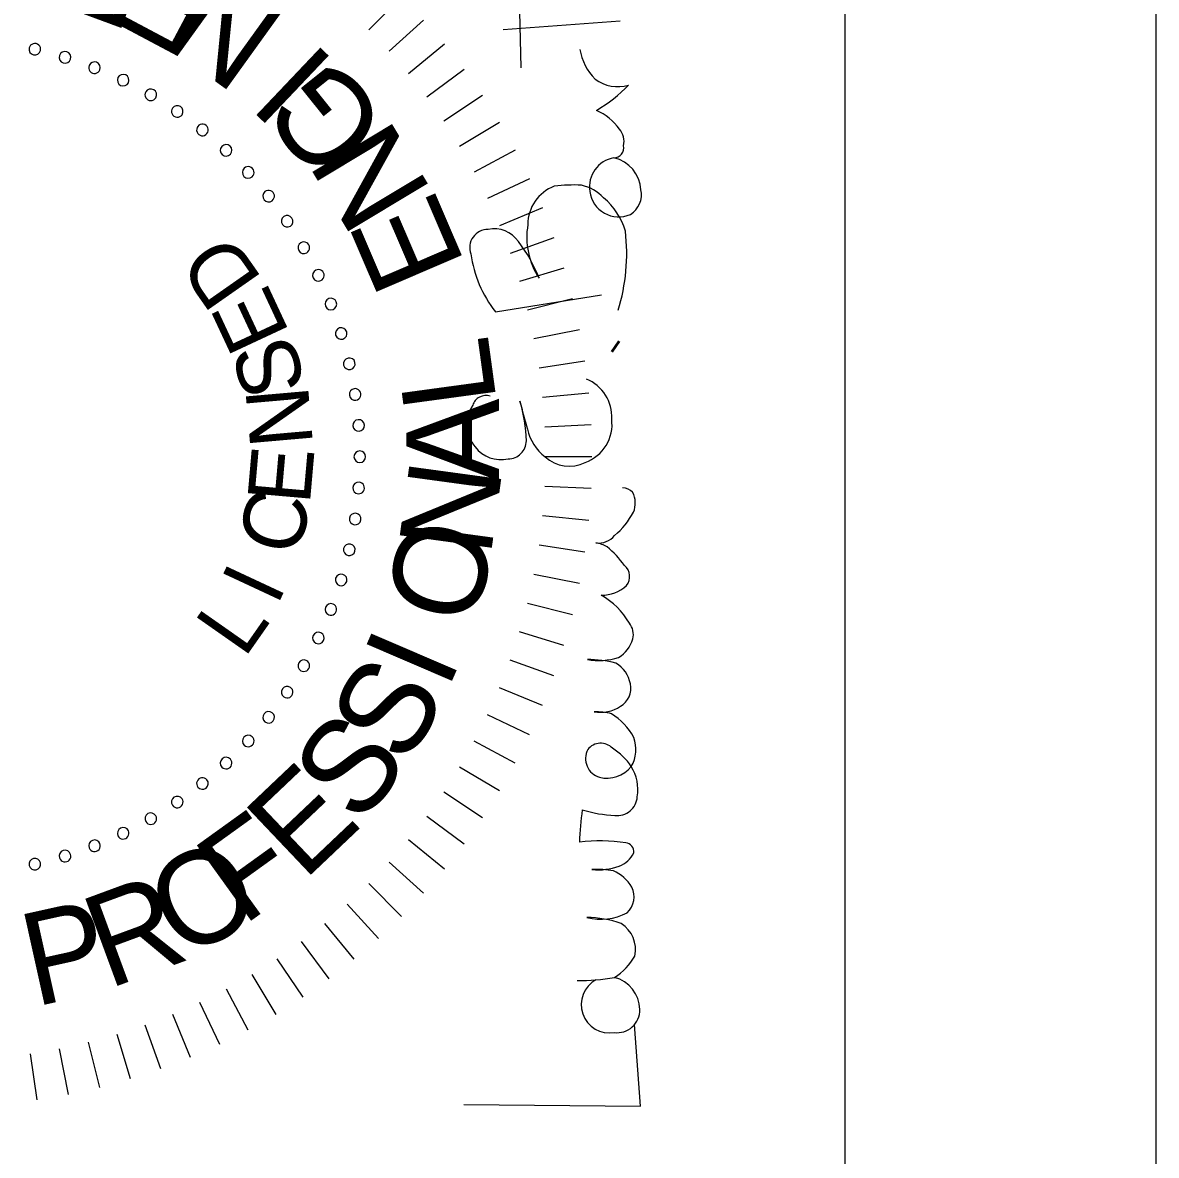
# Model space of a CAD drawing. Extents: x 916887 to 917745, y 329243 to 329793.
# Drawn here: x 917702.44 to 917737.16, y 329615.23 to 329649.92 of the extents above; entities that cross this region are included whole.
import ezdxf

# ---------------------------------------------------------------- set-up
doc = ezdxf.new("R2010")
doc.units = 0
for name, color, linetype in [('Border', 7, 'Continuous'), ('Default', 7, 'Continuous'), ('PLOT BOUNDARY', 7, 'Continuous')]:
    doc.layers.add(name, color=color, linetype=linetype)

# ---------------------------------------------------------------- blocks, each defined once
blk = doc.blocks.new('STAMP')
at = {"layer": 'Default'}
for p, q in [((-0.007878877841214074, 0.0003312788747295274), (-0.0073161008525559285, 0.00041475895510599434)), ((-0.007812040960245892, -5.391156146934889e-05), (-0.007254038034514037, 5.708212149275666e-05)), ((-0.0077263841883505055, -0.0004353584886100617), (-0.0071744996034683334, -0.00029711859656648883)), ((-0.007622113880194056, -0.0008121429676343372), (-0.007077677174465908, -0.0006469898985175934)), ((-0.00749948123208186, -0.0011833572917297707), (-0.0069638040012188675, -0.00099168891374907)), ((-0.007358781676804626, -0.0015481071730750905), (-0.006833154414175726, -0.001330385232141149)), ((-0.007200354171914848, -0.0019055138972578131), (-0.006686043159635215, -0.0016622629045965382)), ((-0.007024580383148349, -0.0022547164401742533), (-0.0065228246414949, -0.001986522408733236)), ((-0.006831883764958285, -0.002594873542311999), (-0.006343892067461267, -0.0023023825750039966)), ((-0.006622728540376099, -0.002925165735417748), (-0.0061496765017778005, -0.0026090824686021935)), ((-0.00639761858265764, -0.0032447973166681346), (-0.005940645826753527, -0.0029058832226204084)), ((-0.006157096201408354, -0.003552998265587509), (-0.005717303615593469, -0.0031920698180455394)), ((-0.005901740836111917, -0.003849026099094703), (-0.005480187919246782, -0.0034669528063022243)), ((-0.0056321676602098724, -0.0041321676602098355), (-0.00522986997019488, -0.003729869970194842)), ((0.00563216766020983, -0.0041321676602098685), (0.0052298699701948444, -0.0037298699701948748)), ((-0.005349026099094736, -0.004401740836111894), (-0.004966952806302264, -0.003980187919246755)), ((0.005349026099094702, -0.004401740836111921), (0.004966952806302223, -0.003980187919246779)), ((-0.0050529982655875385, -0.004657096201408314), (-0.004692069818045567, -0.004217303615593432)), ((0.005052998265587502, -0.004657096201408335), (0.004692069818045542, -0.004217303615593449)), ((-0.004744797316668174, -0.0048976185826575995), (-0.004405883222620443, -0.004440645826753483)), ((0.004744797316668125, -0.0048976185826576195), (0.004405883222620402, -0.0044406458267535)), ((-0.0044251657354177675, -0.005122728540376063), (-0.004109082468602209, -0.004649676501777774)), ((0.004425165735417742, -0.00512272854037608), (0.004109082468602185, -0.004649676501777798)), ((-0.004094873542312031, -0.005331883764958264), (-0.0038023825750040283, -0.004843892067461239)), ((0.0040948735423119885, -0.005331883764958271), (0.003802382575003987, -0.004843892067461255)), ((-0.0037547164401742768, -0.005524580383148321), (-0.0034865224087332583, -0.005022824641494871)), ((0.0037547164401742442, -0.005524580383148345), (0.003486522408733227, -0.005022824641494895)), ((-0.003405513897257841, -0.005700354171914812), (-0.0031622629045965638, -0.0051860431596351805)), ((0.0034055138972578, -0.005700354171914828), (0.003162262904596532, -0.005186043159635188)), ((-0.003048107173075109, -0.005858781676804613), (-0.0028303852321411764, -0.005333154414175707)), ((0.003048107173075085, -0.005858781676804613), (0.002830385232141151, -0.005333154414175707)), ((0.00523613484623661, -0.005376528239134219), (0.005338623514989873, -0.0068089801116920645)), ((-0.0026833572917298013, -0.005999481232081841), (-0.002491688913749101, -0.005463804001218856)), ((0.002683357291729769, -0.005999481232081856), (0.0024916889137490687, -0.005463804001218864)), ((-0.0023121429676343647, -0.006122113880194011), (-0.0021469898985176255, -0.005577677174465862)), ((-0.0019353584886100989, -0.006226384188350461), (-0.0017971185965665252, -0.005674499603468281)), ((0.0019353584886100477, -0.006226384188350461), (0.0017971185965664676, -0.005674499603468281)), ((0.0023121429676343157, -0.006122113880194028), (0.0021469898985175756, -0.005577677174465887)), ((0.004764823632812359, -0.005597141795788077), (0.005863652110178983, -0.005572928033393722)), ((-0.0015539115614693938, -0.006312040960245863), (-0.0014429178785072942, -0.005754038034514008)), ((-0.001168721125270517, -0.006378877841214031), (-0.0010852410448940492, -0.005816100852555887)), ((0.0011687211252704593, -0.006378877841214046), (0.0010852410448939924, -0.005816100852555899)), ((0.0015539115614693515, -0.006312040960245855), (0.0014429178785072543, -0.005754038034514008)), ((-0.0007807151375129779, -0.006426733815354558), (-0.0007249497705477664, -0.0058605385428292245)), ((-0.00039082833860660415, -0.006455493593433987), (-0.00036291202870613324, -0.005887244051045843)), ((-2.0539125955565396e-17, -0.006465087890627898), (-2.0539125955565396e-17, -0.005896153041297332)), ((0.0003908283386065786, -0.0064554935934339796), (0.0003629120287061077, -0.005887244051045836)), ((0.0007807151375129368, -0.006426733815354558), (0.0007249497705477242, -0.005860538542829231)), ((0.001282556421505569, -0.006716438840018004), (0.001411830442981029, -0.006805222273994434)), ((0.0012888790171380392, -0.0067038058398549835), (0.0014181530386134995, -0.006792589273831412))]:
    blk.add_line(p, q, dxfattribs=at)
for points in [[(-0.007938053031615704, -0.004895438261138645), (-0.007956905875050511, -0.007061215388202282), (-0.0069577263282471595, -0.006985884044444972)], [(0.0017747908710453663, -0.005281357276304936), (0.001982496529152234, -0.006583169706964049)]]:
    blk.add_lwpolyline(points, dxfattribs=at)
for centre, radius, start, end in [((-0.0049920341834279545, 0.00036060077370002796), 7.11168561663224e-05, 102.8571428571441, 282.8571428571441), ((-0.0049920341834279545, 0.00036060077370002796), 7.11168561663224e-05, 282.8571428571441, 102.85714285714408), ((0.004992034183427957, 0.00036060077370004), 7.111685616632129e-05, 77.14285714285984, 257.14285714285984), ((0.004992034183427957, 0.00036060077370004), 7.111685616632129e-05, 257.14285714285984, 77.14285714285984), ((-0.004892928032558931, -9.26841668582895e-06), 7.111685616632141e-05, 107.14285714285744, 287.14285714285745), ((-0.004892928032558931, -9.26841668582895e-06), 7.111685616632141e-05, 287.14285714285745, 107.14285714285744), ((0.004892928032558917, -9.268416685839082e-06), 7.111685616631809e-05, 72.85714285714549, 252.8571428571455), ((0.004892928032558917, -9.268416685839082e-06), 7.111685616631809e-05, 252.85714285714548, 72.85714285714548), ((-0.004766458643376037, -0.00037069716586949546), 7.111685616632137e-05, 111.42857142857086, 291.4285714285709), ((-0.004766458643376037, -0.00037069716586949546), 7.111685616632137e-05, 291.4285714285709, 111.42857142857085), ((0.0047664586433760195, -0.00037069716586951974), 7.111685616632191e-05, 68.57142857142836, 248.57142857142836), ((0.0047664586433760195, -0.00037069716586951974), 7.111685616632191e-05, 248.57142857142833, 68.57142857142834), ((-0.0046133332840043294, -0.0007216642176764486), 7.1116856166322e-05, 115.71428571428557, 295.71428571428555), ((-0.0046133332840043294, -0.0007216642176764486), 7.1116856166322e-05, 295.71428571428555, 115.71428571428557), ((0.0046133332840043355, -0.0007216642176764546), 7.111685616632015e-05, 64.28571428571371, 244.2857142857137), ((0.0046133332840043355, -0.0007216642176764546), 7.111685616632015e-05, 244.2857142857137, 64.2857142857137), ((-0.004434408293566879, -0.0010602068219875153), 7.111685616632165e-05, 119.99999999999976, 299.9999999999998), ((-0.004434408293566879, -0.0010602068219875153), 7.111685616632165e-05, 299.9999999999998, 119.99999999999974), ((0.00443440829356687, -0.0010602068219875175), 7.111685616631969e-05, 59.99999999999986, 239.99999999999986), ((0.00443440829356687, -0.0010602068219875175), 7.111685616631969e-05, 239.99999999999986, 59.99999999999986), ((-0.004230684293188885, -0.0013844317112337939), 7.111685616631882e-05, 124.28571428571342, 304.2857142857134), ((-0.004230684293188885, -0.0013844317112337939), 7.111685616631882e-05, 304.2857142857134, 124.28571428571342), ((0.004230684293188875, -0.0013844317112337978), 7.111685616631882e-05, 55.714285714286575, 235.71428571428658), ((0.004230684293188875, -0.0013844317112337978), 7.111685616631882e-05, 235.71428571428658, 55.714285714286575), ((-0.004003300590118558, -0.0016925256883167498), 7.111685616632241e-05, 128.57142857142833, 308.5714285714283), ((-0.004003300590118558, -0.0016925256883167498), 7.111685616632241e-05, 308.5714285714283, 128.57142857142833), ((0.004003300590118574, -0.0016925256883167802), 7.111685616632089e-05, 51.42857142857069, 231.4285714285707), ((0.004003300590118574, -0.0016925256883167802), 7.111685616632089e-05, 231.42857142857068, 51.42857142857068), ((-0.003753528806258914, -0.0019827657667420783), 7.11168561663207e-05, 132.85714285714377, 312.8571428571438), ((-0.003753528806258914, -0.0019827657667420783), 7.11168561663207e-05, 312.85714285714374, 132.85714285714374), ((0.003753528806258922, -0.0019827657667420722), 7.111685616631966e-05, 47.14285714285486, 227.14285714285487), ((0.003753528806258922, -0.0019827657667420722), 7.111685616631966e-05, 227.14285714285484, 47.14285714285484), ((-0.0034827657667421, -0.002253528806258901), 7.111685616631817e-05, 137.14285714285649, 317.1428571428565), ((-0.0034827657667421, -0.002253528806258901), 7.111685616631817e-05, 317.1428571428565, 137.14285714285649), ((0.0034827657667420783, -0.0022535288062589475), 7.111685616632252e-05, 42.857142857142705, 222.85714285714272), ((0.0034827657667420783, -0.0022535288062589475), 7.111685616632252e-05, 222.8571428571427, 42.85714285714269), ((-0.0031925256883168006, -0.0025033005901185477), 7.111685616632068e-05, 141.42857142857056, 321.42857142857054), ((-0.0031925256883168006, -0.0025033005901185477), 7.111685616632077e-05, 321.42857142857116, 141.4285714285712), ((0.0031925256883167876, -0.002503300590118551), 7.111685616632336e-05, 38.57142857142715, 218.57142857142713), ((0.0031925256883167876, -0.002503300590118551), 7.111685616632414e-05, 218.57142857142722, 38.57142857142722), ((-0.0028844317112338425, -0.0027306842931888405), 7.111685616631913e-05, 145.7142857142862, 325.71428571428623), ((-0.0028844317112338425, -0.0027306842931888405), 7.111685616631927e-05, 325.7142857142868, 145.71428571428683), ((0.002884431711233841, -0.0027306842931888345), 7.111685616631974e-05, 34.28571428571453, 214.28571428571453), ((0.002884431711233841, -0.0027306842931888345), 7.111685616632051e-05, 214.28571428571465, 34.28571428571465), ((-0.0025602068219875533, -0.0029344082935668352), 7.111685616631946e-05, 149.99999999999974, 329.9999999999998), ((-0.0025602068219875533, -0.0029344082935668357), 7.111685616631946e-05, 329.9999999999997, 149.99999999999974), ((0.0025602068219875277, -0.0029344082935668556), 7.111685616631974e-05, 30.000000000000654, 210.00000000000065), ((0.0025602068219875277, -0.002934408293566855), 7.111685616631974e-05, 210.00000000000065, 30.000000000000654), ((-0.0022216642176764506, -0.0031133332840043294), 7.111685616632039e-05, 334.2857142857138, 154.2857142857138), ((0.0022216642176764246, -0.0031133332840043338), 7.111685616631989e-05, 25.714285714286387, 205.71428571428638), ((-0.0022216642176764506, -0.0031133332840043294), 7.111685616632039e-05, 154.2857142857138, 334.28571428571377), ((0.0022216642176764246, -0.0031133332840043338), 7.111685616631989e-05, 205.71428571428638, 25.714285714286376), ((-0.0018706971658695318, -0.003266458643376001), 7.111685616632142e-05, 158.57142857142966, 338.5714285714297), ((-0.0018706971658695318, -0.0032664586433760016), 7.111685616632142e-05, 338.57142857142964, 158.57142857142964), ((-0.0015092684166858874, -0.003392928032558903), 7.111685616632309e-05, 342.85714285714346, 162.85714285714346), ((0.0015092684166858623, -0.0033929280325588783), 7.111685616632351e-05, 17.142857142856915, 197.1428571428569), ((0.0018706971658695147, -0.0032664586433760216), 7.111685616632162e-05, 21.428571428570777, 201.42857142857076), ((0.0018706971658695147, -0.0032664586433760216), 7.111685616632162e-05, 201.42857142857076, 21.428571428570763), ((-0.0015092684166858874, -0.003392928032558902), 7.111685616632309e-05, 162.85714285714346, 342.85714285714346), ((-0.0011393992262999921, -0.0034920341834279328), 7.111685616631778e-05, 347.14285714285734, 167.14285714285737), ((0.0011393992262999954, -0.0034920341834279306), 7.111685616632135e-05, 12.857142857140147, 192.85714285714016), ((0.0015092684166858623, -0.0033929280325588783), 7.111685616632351e-05, 197.1428571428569, 17.14285714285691), ((-0.0011393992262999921, -0.0034920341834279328), 7.111685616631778e-05, 167.14285714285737, 347.14285714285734), ((-0.0007631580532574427, -0.003563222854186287), 7.111685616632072e-05, 171.4285714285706, 351.4285714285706), ((-0.0007631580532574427, -0.003563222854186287), 7.111685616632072e-05, 351.4285714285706, 171.4285714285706), ((-0.0003826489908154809, -0.003606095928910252), 7.111685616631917e-05, 175.71428571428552, 355.71428571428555), ((-0.0003826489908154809, -0.003606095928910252), 7.111685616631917e-05, 355.7142857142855, 175.7142857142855), ((-1.2628786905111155e-17, -0.0036204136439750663), 7.111685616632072e-05, 0, 180), ((0.0003826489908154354, -0.0036060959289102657), 7.111685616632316e-05, 4.285714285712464, 184.28571428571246), ((0.0003826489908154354, -0.0036060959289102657), 7.111685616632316e-05, 184.28571428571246, 4.285714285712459), ((0.0007631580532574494, -0.0035632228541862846), 7.111685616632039e-05, 8.571428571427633, 188.57142857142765), ((0.0007631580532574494, -0.0035632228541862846), 7.111685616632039e-05, 188.57142857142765, 8.571428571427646), ((0.0011393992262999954, -0.0034920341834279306), 7.111685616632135e-05, 192.85714285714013, 12.857142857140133), ((-1.2628786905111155e-17, -0.0036204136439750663), 7.111685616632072e-05, 180, 0), ((0.00039604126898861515, -0.005375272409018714), 0.00043958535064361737, 57.64755033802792, 128.97245422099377), ((0.0027009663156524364, -0.006477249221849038), 0.001512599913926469, 98.17812986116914, 127.75649827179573), ((0.0025607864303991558, -0.005191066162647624), 0.0002239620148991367, 359.61429023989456, 109.56218572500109), ((0.00036114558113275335, -0.0053488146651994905), 0.0003972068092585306, 127.45926190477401, 192.9614203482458), ((0.0005805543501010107, -0.005165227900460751), 0.00016909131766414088, 342.3611945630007, 72.54487353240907), ((0.0024288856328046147, -0.00526578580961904), 0.0003633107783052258, 304.8740098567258, 11.625468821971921), ((0.00019608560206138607, -0.005439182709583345), 0.0002220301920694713, 179.67057284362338, 269.694601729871), ((0.0004564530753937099, -0.0062299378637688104), 0.0005678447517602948, 102.0773813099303, 143.39383108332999), ((0.00015503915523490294, -0.003868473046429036), 0.001793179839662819, 271.2738092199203, 287.01217780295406), ((0.002166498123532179, -0.011827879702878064), 0.006419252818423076, 103.3923944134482, 106.55297850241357), ((0.0015502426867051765, -0.00415818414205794), 0.0017765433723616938, 290.99837671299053, 307.69878588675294), ((0.0026896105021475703, -0.006582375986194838), 0.0009159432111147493, 80.29637939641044, 123.29138431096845), ((0.0028457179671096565, -0.006179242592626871), 0.0004997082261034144, 20.58705533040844, 90.19763829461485), ((0.00031613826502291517, -0.006186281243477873), 0.0004319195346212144, 136.9297266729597, 206.7934360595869), ((0.0014539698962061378, -0.006245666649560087), 0.0018752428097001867, 357.2040173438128, 7.418903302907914), ((-0.00671307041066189, -0.006678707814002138), 0.0003465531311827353, 28.430349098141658, 189.68707560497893), ((-0.003955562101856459, -0.006312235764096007), 0.002461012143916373, 179.30402472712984, 190.0665804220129), ((-0.007015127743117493, -0.0065631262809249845), 0.0023079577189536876, 352.1195763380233, 6.249520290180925), ((-0.004786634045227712, -0.009314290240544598), 0.003003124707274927, 81.15725195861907, 88.74550427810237), ((-0.002857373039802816, -0.006810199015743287), 0.001539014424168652, 162.47862001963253, 177.5735090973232), ((-0.0037000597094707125, -0.006623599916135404), 0.00023723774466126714, 61.91684207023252, 163.66717131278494), ((0.0003962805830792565, -0.006217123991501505), 0.0004936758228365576, 199.38474076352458, 277.55079490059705), ((0.0027994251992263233, -0.006216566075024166), 0.0005411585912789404, 313.71200852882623, 347.12598992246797), ((0.005109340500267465, -0.0069995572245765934), 0.000693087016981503, 99.83623703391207, 134.2279465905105), ((-0.007040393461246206, -0.006369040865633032), 0.0013973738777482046, 341.03759348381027, 358.5906169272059), ((-0.004987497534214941, -0.006577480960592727), 0.0006786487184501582, 165.1377733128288, 207.96825790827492), ((-0.006329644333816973, -0.006519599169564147), 0.0012732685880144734, 350.5388137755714, 2.446920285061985), ((-0.004310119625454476, -0.006538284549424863), 0.0007509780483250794, 174.41813129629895, 200.30191948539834), ((-0.0037052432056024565, -0.0065716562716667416), 0.0001960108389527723, 312.7382758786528, 53.40100716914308), ((-0.003974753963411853, -0.006503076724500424), 0.0008496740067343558, 346.26214121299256, 0.7257075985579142), ((-0.002682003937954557, -0.006568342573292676), 0.00044961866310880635, 170.2648919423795, 213.2954708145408), ((-0.00388024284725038, -0.006412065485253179), 0.0013948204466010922, 345.72048696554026, 0.12433676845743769), ((-0.0016914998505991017, -0.006545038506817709), 0.0008054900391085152, 170.27954956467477, 197.78532003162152), ((-0.0013865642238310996, -0.006474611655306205), 0.0003320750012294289, 327.8843366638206, 353.1980671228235), ((-0.0008025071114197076, -0.006544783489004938), 0.0002561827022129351, 173.08541670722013, 230.55848375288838), ((0.0004891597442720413, -0.006207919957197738), 0.0004993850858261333, 266.784921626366, 337.7362429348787), ((0.0032953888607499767, -0.006791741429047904), 0.00035634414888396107, 97.37079091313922, 203.8922211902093), ((0.0033059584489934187, -0.006794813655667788), 0.0003608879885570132, 9.655140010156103, 98.97262191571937), ((0.003588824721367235, -0.00621969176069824), 0.0007209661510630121, 306.1913846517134, 335.23134174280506), ((0.005998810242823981, -0.005456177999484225), 0.0020534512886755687, 211.2594929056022, 225.2513717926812), ((0.004994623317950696, -0.006780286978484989), 0.0004614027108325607, 143.047197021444, 196.91634387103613), ((-0.0035430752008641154, -0.006644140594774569), 0.0003944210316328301, 167.2189950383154, 230.16055614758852), ((-0.002536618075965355, -0.006083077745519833), 0.0009765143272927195, 300.6803608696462, 329.51258202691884), ((-0.0012666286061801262, -0.006594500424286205), 0.00042878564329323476, 177.86300386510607, 223.17874837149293), ((-0.0020051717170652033, -0.0059200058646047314), 0.0011594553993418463, 305.5205731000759, 320.90595982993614), ((0.002532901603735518, -0.0060711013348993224), 0.0008355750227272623, 286.05704557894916, 320.0421489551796), ((-0.006777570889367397, -0.006772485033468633), 0.00027937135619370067, 172.70712454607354, 271.16395527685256), ((-0.006783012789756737, -0.006633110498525), 0.0004188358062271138, 271.5209447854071, 344.87406906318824), ((-0.005754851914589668, -0.006345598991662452), 0.0007393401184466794, 212.4592088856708, 240.63114206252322), ((-0.0055308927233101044, -0.006522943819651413), 0.0005014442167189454, 301.1133493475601, 335.74975916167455), ((-0.004715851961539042, -0.006689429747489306), 0.00031800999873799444, 200.1253724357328, 244.48124886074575), ((-0.004152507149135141, -0.006775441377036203), 0.00024439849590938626, 172.85451562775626, 266.8151593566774), ((-0.00421927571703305, -0.006314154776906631), 0.0007614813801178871, 303.79189499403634, 328.18256979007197), ((-0.0038004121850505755, -0.006299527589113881), 0.000766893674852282, 298.0105046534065, 328.09350966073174), ((-0.00285343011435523, -0.006566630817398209), 0.0003761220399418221, 280.5798823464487, 329.7517392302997), ((-0.0021179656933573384, -0.00658432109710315), 0.00039838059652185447, 211.26450698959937, 253.32703764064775), ((-0.0001785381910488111, -0.0060637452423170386), 0.0010391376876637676, 220.79179678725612, 241.16030041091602), ((0.0024869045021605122, -0.0045618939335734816), 0.0023287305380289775, 252.701645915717, 276.8342307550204), ((0.0032445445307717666, -0.006637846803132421), 0.00042819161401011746, 273.5716384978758, 346.98387133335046), ((0.0037841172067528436, -0.006733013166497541), 0.00012238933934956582, 180.59606692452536, 282.14231124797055), ((0.0038601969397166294, -0.006618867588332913), 0.000239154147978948, 257.8497316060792, 310.1947013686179), ((-0.006036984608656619, -0.006622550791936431), 0.0003760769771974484, 257.6460165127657, 327.7710077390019), ((-0.005391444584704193, -0.006712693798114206), 0.0002677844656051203, 223.12676578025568, 296.5429712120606), ((-0.004842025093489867, -0.006862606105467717), 0.00011432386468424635, 264.56536252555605, 351.47104640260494), ((-0.0028340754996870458, -0.006679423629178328), 0.00026169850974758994, 211.24435430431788, 280.94854976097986), ((-0.0021804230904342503, -0.006741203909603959), 0.00023065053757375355, 257.01114107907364, 308.02112433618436), ((-0.0014677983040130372, -0.006749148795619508), 0.0001780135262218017, 231.21384232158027, 319.94914487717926), ((-0.0005623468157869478, -0.006834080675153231), 0.00018159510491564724, 314.66347430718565, 358.2957841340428), ((0.003211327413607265, -0.006788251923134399), 0.0002833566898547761, 211.44349084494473, 282.2024112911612), ((-0.00407546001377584, -0.006500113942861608), 0.0005271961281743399, 260.1016649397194, 302.042575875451), ((-0.0035868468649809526, -0.00658750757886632), 0.00041578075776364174, 239.8376850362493, 290.64484911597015), ((-0.0005688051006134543, -0.006705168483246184), 0.00029083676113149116, 247.5695171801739, 297.4590386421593)]:
    blk.add_arc(centre, radius, start, end, dxfattribs=at)
for s, height, rotation, p in [('P', 0.0011378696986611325, 282.5, (-0.006741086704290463, 0.00036378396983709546)), ('E', 0.0011378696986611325, 69.75, (0.006276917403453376, -0.001210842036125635)), ('R', 0.0011378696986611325, 290.25, (-0.00652629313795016, -0.0005348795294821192)), ('E', 0.0011378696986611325, 62, (0.005854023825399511, -0.002032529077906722)), ('O', 0.0011378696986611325, 298, (-0.006169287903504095, -0.0014396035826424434)), ('N', 0.001137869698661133, 54.25000000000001, (0.005352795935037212, -0.0027499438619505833)), ('D', 0.0007680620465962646, 34.99999999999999, (0.002169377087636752, -0.0024365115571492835)), ('F', 0.001137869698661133, 305.75, (-0.0057573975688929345, -0.002187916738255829)), ('L', 0.0007680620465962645, 324.99999999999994, (-0.002479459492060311, -0.00220631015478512)), ('E', 0.0007680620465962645, 25.000000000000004, (0.001513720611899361, -0.002766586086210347)), ('I', 0.0007680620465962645, 335, (-0.001841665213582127, -0.002604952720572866)), ('C', 0.0007680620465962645, 345, (-0.0012469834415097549, -0.0028524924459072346)), ('S', 0.0007680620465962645, 14.999999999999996, (0.0008506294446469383, -0.0029637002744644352)), ('E', 0.0011378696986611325, 313.5, (-0.005207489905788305, -0.0029306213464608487)), ('E', 0.0007680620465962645, 355, (-0.0005969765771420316, -0.00300722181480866)), ('N', 0.0007680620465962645, 5, (0.0001499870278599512, -0.003047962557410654)), ('I', 0.001137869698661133, 46.499999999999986, (0.004817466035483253, -0.003341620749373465)), ('G', 0.001137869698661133, 38.75000000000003, (0.004038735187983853, -0.004012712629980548)), ('S', 0.0011378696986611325, 321.25, (-0.004535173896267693, -0.0036142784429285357)), ('N', 0.0011378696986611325, 30.999999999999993, (0.0032404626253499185, -0.004517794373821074)), ('S', 0.0011378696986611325, 328.99999999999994, (-0.003804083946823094, -0.004179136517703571)), ('E', 0.0011378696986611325, 23.249999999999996, (0.0023543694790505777, -0.004919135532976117)), ('I', 0.0011378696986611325, 336.75, (-0.0028749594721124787, -0.00469547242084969)), ('O', 0.001137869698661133, 344.5, (-0.0021143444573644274, -0.004998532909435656)), ('N', 0.001137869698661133, 352.25, (-0.001239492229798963, -0.005221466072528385)), ('L', 0.001137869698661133, 7.75, (0.0006711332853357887, -0.0052988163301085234))]:
    blk.add_text(s, height=height, rotation=rotation, dxfattribs=at).set_placement(p)
blk.add_text('A', height=0.0011378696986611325, dxfattribs=at).set_placement((-0.0003007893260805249, -0.005327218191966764))

msp = doc.modelspace()

# ---------------------------------------------------------------- linework, layer by layer
at = {"layer": 'Border'}
msp.add_line((917727.630894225, 329258.0107371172), (917727.630894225, 329783.00968711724), dxfattribs=at)
at = {"layer": 'PLOT BOUNDARY'}
msp.add_lwpolyline([(916887.1658435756, 329242.7002039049), (917737.1641435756, 329242.7002039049), (917737.1641435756, 329792.6991039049), (916887.1658435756, 329792.6991039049)], close=True, dxfattribs=at)

# ---------------------------------------------------------------- block references
at = {"layer": 'Border', "xscale": 2499.999999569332, "yscale": 2499.999999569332, "rotation": 90}
msp.add_blockref('STAMP', (917703.7166483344, 329636.6288155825), dxfattribs=at)

doc.saveas('drawing.dxf')
